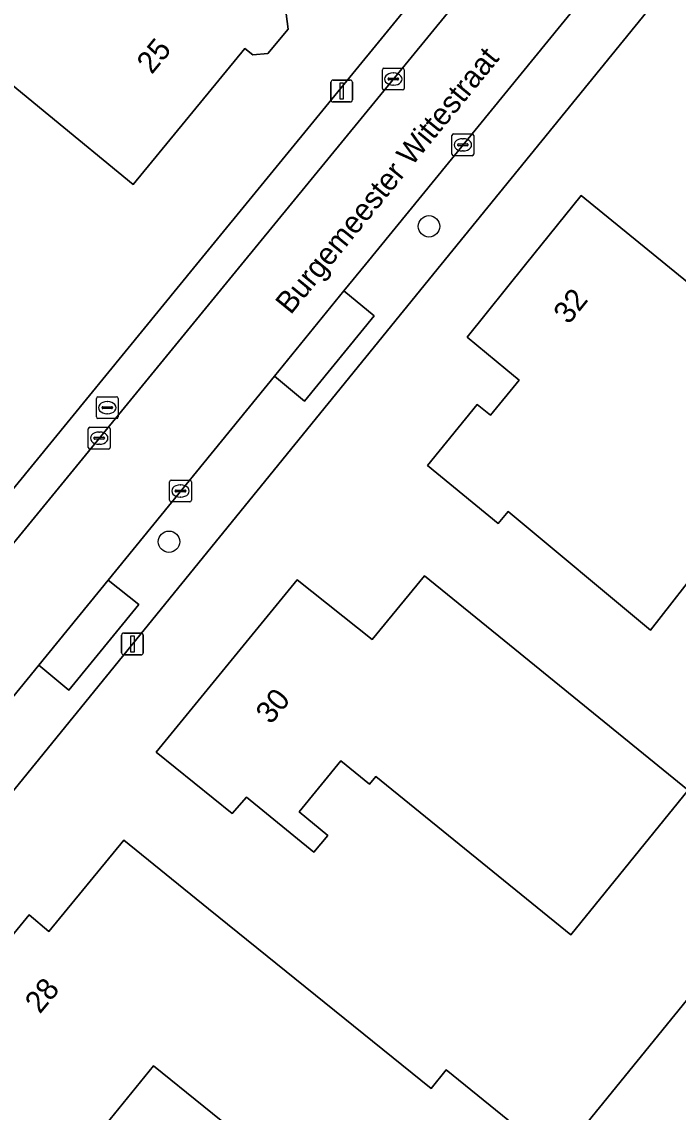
# Model space of a CAD drawing. Extents: x 159499 to 160349, y 382524 to 383273.
# Drawn here: x 160016.05 to 160046.07, y 382961.2 to 383011.11 of the extents above; entities that cross this region are included whole.
import ezdxf

# ---------------------------------------------------------------- set-up
doc = ezdxf.new("R2010")
doc.units = 0
for name, color, linetype in [('IMGEO_Boom', 7, 'Continuous'), ('IMGEO_Brandkraan', 7, 'Continuous'), ('IMGEO_Erf', 7, 'Continuous'), ('IMGEO_Groenvoorziening', 7, 'Continuous'), ('IMGEO_Kolk', 7, 'Continuous'), ('IMGEO_Lichtmast', 7, 'Continuous'), ('IMGEO_Openbare_ruimte_label', 7, 'Continuous'), ('IMGEO_Pand', 7, 'Continuous'), ('IMGEO_Pand_nummerreeks', 7, 'Continuous'), ('IMGEO_Parkeervlak_open', 7, 'Continuous'), ('IMGEO_Rijbaan_lokaal_open', 7, 'Continuous'), ('IMGEO_Voetpad_open', 7, 'Continuous')]:
    doc.layers.add(name, color=color, linetype=linetype)

msp = doc.modelspace()

# ---------------------------------------------------------------- linework, layer by layer
at = {"layer": 'IMGEO_Boom'}
for centre in [(160034.675, 383001.749), (160022.782, 382987.311)]:
    msp.add_circle(centre, 0.489, dxfattribs=at)
at = {"layer": 'IMGEO_Brandkraan'}
for p, q in [((160019.46, 382993.024), (160019.46, 382993.876)), ((160019.535, 382993.95), (160020.387, 382993.95)), ((160020.461, 382993.876), (160020.461, 382993.024)), ((160019.719, 382993.444), (160019.719, 382993.456)), ((160020.157, 382993.407), (160019.759, 382993.407)), ((160019.762, 382993.493), (160020.16, 382993.493)), ((160019.948, 382993.73), (160019.973, 382993.73)), ((160020.203, 382993.456), (160020.203, 382993.444)), ((160020.387, 382992.95), (160019.535, 382992.95)), ((160019.971, 382993.17), (160019.946, 382993.17))]:
    msp.add_line(p, q, dxfattribs=at)
for points in [[(160019.46, 382993.024), (160019.46, 382993.876)], [(160019.535, 382993.95), (160020.387, 382993.95)], [(160020.461, 382993.876), (160020.461, 382993.024)], [(160020.387, 382992.95), (160019.535, 382992.95)]]:
    msp.add_lwpolyline(points, dxfattribs=at)
for centre, radius, start, end in [((160019.537, 382993.874), 0.0765, 91.552, 178.448), ((160019.537, 382993.874), 0.0765, 91.552, 178.448), ((160020.385, 382993.874), 0.0765, 1.552, 88.448), ((160020.385, 382993.874), 0.0765, 1.552, 88.448), ((160019.759, 382993.453), 0.0403, 85.8775, 175.7526), ((160019.756, 382993.443), 0.0366, 178.938, 274.7102), ((160020.16, 382993.45), 0.043, 264.8664, 352.4533), ((160020.164, 382993.455), 0.0386, 1.7309, 96.639), ((160019.537, 382993.026), 0.0765, 181.552, 268.448), ((160019.537, 382993.026), 0.0765, 181.552, 268.448), ((160020.385, 382993.026), 0.0765, 271.552, 358.448), ((160020.385, 382993.026), 0.0765, 271.552, 358.448)]:
    msp.add_arc(centre, radius, start, end, dxfattribs=at)
for centre, major_axis, ratio, start_param, end_param in [((160019.947, 382993.45), (-0.387, 0.002), 0.722429, 4.712389, 7.853982), ((160019.972, 382993.45), (-0.39, 0.002), 0.717154, 1.570796, 4.712389)]:
    msp.add_ellipse(centre, major_axis=major_axis, ratio=ratio, start_param=start_param, end_param=end_param, dxfattribs=at)
at = {"layer": 'IMGEO_Erf'}
for points in [[(160052.413, 382973.653), (160074.019, 383000), (160086.515, 383015.238), (160064.154, 383036.884), (160058.252, 383028.674), (160056.791, 383026.642), (160055.985, 383025.521), (160035.23, 383000), (160013.21, 382972.924), (160006.361, 382964.545)], [(159937.661, 382989.432), (159947.551, 382981.884), (159972.788, 382962.692), (159974.862, 382962.113), (159982.324, 382962.546), (159992.571, 382963.192), (159994.756, 382964.255), (160000, 382970.621), (160005.936, 382977.853), (160024.041, 383000), (160036.566, 383015.316)], [(160028.146, 383011.474), (160028.232, 383010.766), (160027.306, 383009.661), (160026.619, 383009.6), (160026.258, 383009.888), (160021.143, 383003.663), (160017.28, 383006.838), (160013.564, 383009.891), (160017.577, 383014.775)], [(160012.916, 382957.191), (160007.749, 382961.454), (160012.437, 382967.265), (160013.346, 382966.541), (160016.393, 382970.234), (160017.292, 382969.479), (160020.71, 382973.659), (160024.597, 382970.514), (160034.771, 382962.282), (160035.463, 382963.138), (160039.738, 382959.678)], [(160031.009, 382947.305), (160052.413, 382973.653)], [(160031.282, 382955.879), (160022.074, 382963.331), (160017.918, 382958.195)]]:
    msp.add_lwpolyline(points, dxfattribs=at)
for points in [[(160034.602, 382990.807), (160036.885, 382993.599), (160037.483, 382993.104), (160038.802, 382994.704), (160038.198, 382995.204), (160036.42, 382996.676), (160039.09, 383000), (160041.631, 383003.164), (160045.507, 383000), (160054.82, 382992.397), (160051.441, 382988.25), (160049.799, 382989.545), (160048.212, 382987.537), (160048.471, 382987.314), (160047.657, 382986.319), (160047.349, 382986.525), (160044.81, 382983.264), (160038.291, 382988.69), (160037.833, 382988.148)], [(160030.648, 382977.285), (160028.731, 382974.948), (160030.042, 382973.872), (160029.408, 382973.1), (160026.322, 382975.62), (160025.668, 382974.868), (160022.198, 382977.675), (160027.413, 382984.066), (160028.644, 382985.575), (160032.069, 382982.833), (160034.475, 382985.754), (160038.352, 382982.597), (160046.532, 382975.935), (160041.167, 382969.32), (160032.251, 382976.566), (160031.96, 382976.211)]]:
    msp.add_lwpolyline(points, close=True, dxfattribs=at)
at = {"layer": 'IMGEO_Groenvoorziening'}
msp.add_lwpolyline([(160064.767, 383037.736), (160064.154, 383036.884), (160086.515, 383015.238), (160074.019, 383000), (160052.413, 382973.653), (160031.009, 382947.305), (160042.591, 382939.142), (160050.543, 382949.325), (160056.483, 382957.417)], dxfattribs=at)
at = {"layer": 'IMGEO_Kolk'}
for p, q in [((160032.542, 383008.065), (160032.542, 383008.917)), ((160032.617, 383008.991), (160033.469, 383008.991)), ((160033.03, 383008.771), (160033.055, 383008.771)), ((160033.543, 383008.917), (160033.543, 383008.065)), ((160032.801, 383008.485), (160032.801, 383008.497)), ((160033.239, 383008.448), (160032.841, 383008.448)), ((160032.844, 383008.534), (160033.242, 383008.534)), ((160033.285, 383008.497), (160033.285, 383008.485)), ((160033.469, 383007.991), (160032.617, 383007.991)), ((160033.053, 383008.211), (160033.028, 383008.211)), ((160035.724, 383005.053), (160035.724, 383005.905)), ((160035.799, 383005.979), (160036.651, 383005.979)), ((160036.212, 383005.759), (160036.237, 383005.759)), ((160036.725, 383005.905), (160036.725, 383005.053)), ((160035.983, 383005.473), (160035.983, 383005.485)), ((160036.421, 383005.436), (160036.023, 383005.436)), ((160036.026, 383005.522), (160036.424, 383005.522)), ((160036.467, 383005.485), (160036.467, 383005.473)), ((160036.651, 383004.979), (160035.799, 383004.979)), ((160036.235, 383005.199), (160036.21, 383005.199)), ((160019.09, 382991.629), (160019.09, 382992.481)), ((160019.165, 382992.555), (160020.017, 382992.555)), ((160019.578, 382992.335), (160019.603, 382992.335)), ((160020.091, 382992.481), (160020.091, 382991.629)), ((160019.349, 382992.049), (160019.349, 382992.061)), ((160019.787, 382992.012), (160019.389, 382992.012)), ((160019.392, 382992.098), (160019.79, 382992.098)), ((160019.601, 382991.775), (160019.576, 382991.775)), ((160019.833, 382992.061), (160019.833, 382992.049)), ((160020.017, 382991.555), (160019.165, 382991.555)), ((160022.808, 382989.209), (160022.808, 382990.061)), ((160022.883, 382990.135), (160023.735, 382990.135)), ((160023.296, 382989.915), (160023.321, 382989.915)), ((160023.809, 382990.061), (160023.809, 382989.209)), ((160023.067, 382989.629), (160023.067, 382989.641)), ((160023.505, 382989.592), (160023.107, 382989.592)), ((160023.11, 382989.678), (160023.508, 382989.678)), ((160023.319, 382989.355), (160023.294, 382989.355)), ((160023.551, 382989.641), (160023.551, 382989.629)), ((160023.735, 382989.135), (160022.883, 382989.135))]:
    msp.add_line(p, q, dxfattribs=at)
for points in [[(160032.542, 383008.065), (160032.542, 383008.917)], [(160032.617, 383008.991), (160033.469, 383008.991)], [(160033.543, 383008.917), (160033.543, 383008.065)], [(160033.469, 383007.991), (160032.617, 383007.991)], [(160035.724, 383005.053), (160035.724, 383005.905)], [(160035.799, 383005.979), (160036.651, 383005.979)], [(160036.725, 383005.905), (160036.725, 383005.053)], [(160036.651, 383004.979), (160035.799, 383004.979)], [(160019.09, 382991.629), (160019.09, 382992.481)], [(160019.165, 382992.555), (160020.017, 382992.555)], [(160020.091, 382992.481), (160020.091, 382991.629)], [(160020.017, 382991.555), (160019.165, 382991.555)], [(160022.808, 382989.209), (160022.808, 382990.061)], [(160022.883, 382990.135), (160023.735, 382990.135)], [(160023.809, 382990.061), (160023.809, 382989.209)], [(160023.735, 382989.135), (160022.883, 382989.135)]]:
    msp.add_lwpolyline(points, dxfattribs=at)
for centre, radius, start, end in [((160032.619, 383008.915), 0.0765, 91.552, 178.448), ((160032.619, 383008.915), 0.0765, 91.552, 178.448), ((160033.467, 383008.915), 0.0765, 1.552, 88.448), ((160033.467, 383008.915), 0.0765, 1.552, 88.448), ((160032.841, 383008.494), 0.0403, 85.8775, 175.7526), ((160032.838, 383008.484), 0.0366, 178.938, 274.7102), ((160033.242, 383008.491), 0.043, 264.8664, 352.4533), ((160033.246, 383008.496), 0.0386, 1.7309, 96.639), ((160032.619, 383008.067), 0.0765, 181.552, 268.448), ((160032.619, 383008.067), 0.0765, 181.552, 268.448), ((160033.467, 383008.067), 0.0765, 271.552, 358.448), ((160033.467, 383008.067), 0.0765, 271.552, 358.448), ((160035.801, 383005.903), 0.0765, 91.552, 178.448), ((160035.801, 383005.903), 0.0765, 91.552, 178.448), ((160036.649, 383005.903), 0.0765, 1.552, 88.448), ((160036.649, 383005.903), 0.0765, 1.552, 88.448), ((160036.023, 383005.482), 0.0403, 85.8775, 175.7526), ((160036.02, 383005.472), 0.0366, 178.938, 274.7102), ((160036.424, 383005.479), 0.043, 264.8664, 352.4533), ((160036.428, 383005.484), 0.0386, 1.7309, 96.639), ((160035.801, 383005.055), 0.0765, 181.552, 268.448), ((160035.801, 383005.055), 0.0765, 181.552, 268.448), ((160036.649, 383005.055), 0.0765, 271.552, 358.448), ((160036.649, 383005.055), 0.0765, 271.552, 358.448), ((160019.167, 382992.479), 0.0765, 91.552, 178.448), ((160019.167, 382992.479), 0.0765, 91.552, 178.448), ((160020.015, 382992.479), 0.0765, 1.552, 88.448), ((160020.015, 382992.479), 0.0765, 1.552, 88.448), ((160019.389, 382992.058), 0.0403, 85.8775, 175.7526), ((160019.386, 382992.048), 0.0366, 178.938, 274.7102), ((160019.79, 382992.055), 0.043, 264.8664, 352.4533), ((160019.794, 382992.06), 0.0386, 1.7309, 96.639), ((160019.167, 382991.631), 0.0765, 181.552, 268.448), ((160019.167, 382991.631), 0.0765, 181.552, 268.448), ((160020.015, 382991.631), 0.0765, 271.552, 358.448), ((160020.015, 382991.631), 0.0765, 271.552, 358.448), ((160022.885, 382990.059), 0.0765, 91.552, 178.448), ((160022.885, 382990.059), 0.0765, 91.552, 178.448), ((160023.733, 382990.059), 0.0765, 1.552, 88.448), ((160023.733, 382990.059), 0.0765, 1.552, 88.448), ((160023.107, 382989.638), 0.0403, 85.8775, 175.7526), ((160023.104, 382989.628), 0.0366, 178.938, 274.7102), ((160023.508, 382989.635), 0.043, 264.8664, 352.4533), ((160023.512, 382989.64), 0.0386, 1.7309, 96.639), ((160022.885, 382989.211), 0.0765, 181.552, 268.448), ((160022.885, 382989.211), 0.0765, 181.552, 268.448), ((160023.733, 382989.211), 0.0765, 271.552, 358.448), ((160023.733, 382989.211), 0.0765, 271.552, 358.448)]:
    msp.add_arc(centre, radius, start, end, dxfattribs=at)
for centre, major_axis, ratio, start_param, end_param in [((160033.029, 383008.491), (-0.387, 0.002), 0.722429, 4.712389, 7.853982), ((160033.054, 383008.491), (-0.39, 0.002), 0.717154, 1.570796, 4.712389), ((160036.211, 383005.479), (-0.387, 0.002), 0.722429, 4.712389, 7.853982), ((160036.236, 383005.479), (-0.39, 0.002), 0.717154, 1.570796, 4.712389), ((160019.577, 382992.055), (-0.387, 0.002), 0.722429, 4.712389, 7.853982), ((160019.602, 382992.055), (-0.39, 0.002), 0.717154, 1.570796, 4.712389), ((160023.295, 382989.635), (-0.387, 0.002), 0.722429, 4.712389, 7.853982), ((160023.32, 382989.635), (-0.39, 0.002), 0.717154, 1.570796, 4.712389)]:
    msp.add_ellipse(centre, major_axis=major_axis, ratio=ratio, start_param=start_param, end_param=end_param, dxfattribs=at)
at = {"layer": 'IMGEO_Lichtmast'}
for p, q in [((160030.186, 383007.54), (160030.186, 383008.34)), ((160030.186, 383008.34), (160030.186, 383007.54)), ((160030.286, 383008.44), (160031.076, 383008.44)), ((160031.076, 383008.44), (160030.286, 383008.44)), ((160031.176, 383008.34), (160031.176, 383007.54)), ((160031.176, 383007.54), (160031.176, 383008.34)), ((160031.076, 383007.44), (160030.286, 383007.44)), ((160030.286, 383007.44), (160031.076, 383007.44)), ((160020.613, 382982.235), (160020.613, 382983.035)), ((160020.613, 382983.035), (160020.613, 382982.235)), ((160020.713, 382983.135), (160021.503, 382983.135)), ((160021.503, 382983.135), (160020.713, 382983.135)), ((160021.603, 382983.035), (160021.603, 382982.235)), ((160021.603, 382982.235), (160021.603, 382983.035)), ((160021.503, 382982.135), (160020.713, 382982.135)), ((160020.713, 382982.135), (160021.503, 382982.135))]:
    msp.add_line(p, q, dxfattribs=at)
for points in [[(160030.606, 383008.315), (160030.756, 383008.315), (160030.756, 383007.565), (160030.606, 383007.565), (160030.606, 383008.315)], [(160021.033, 382983.01), (160021.183, 382983.01), (160021.183, 382982.26), (160021.033, 382982.26), (160021.033, 382983.01)]]:
    msp.add_lwpolyline(points, dxfattribs=at)
for centre, start, end in [((160030.286, 383008.34), 90, 180), ((160030.286, 383008.34), 90, 180), ((160031.076, 383008.34), 0, 90), ((160031.076, 383008.34), 360, 90), ((160030.286, 383007.54), 180, 270), ((160030.286, 383007.54), 180, 270), ((160031.076, 383007.54), 270, 0), ((160031.076, 383007.54), 270, 0), ((160020.713, 382983.035), 90, 180), ((160020.713, 382983.035), 90, 180), ((160021.503, 382983.035), 0, 90), ((160021.503, 382983.035), 360, 90), ((160020.713, 382982.235), 180, 270), ((160020.713, 382982.235), 180, 270), ((160021.503, 382982.235), 270, 0), ((160021.503, 382982.235), 270, 0)]:
    msp.add_arc(centre, 0.1, start, end, dxfattribs=at)
at = {"layer": 'IMGEO_Pand'}
for points in [[(160026.663, 383014.101), (160026.624, 383014.376), (160028.927, 383017.161), (160028.12, 383017.82), (160025.684, 383019.808), (160023.316, 383021.728), (160021.015, 383018.927), (160018.837, 383018.735), (160017.364, 383016.942), (160017.577, 383014.775), (160013.564, 383009.891), (160017.28, 383006.838), (160021.143, 383003.663), (160026.258, 383009.888), (160026.619, 383009.6), (160027.306, 383009.661), (160028.232, 383010.766), (160028.146, 383011.474), (160026.82, 383012.513)], [(160051.441, 382988.25), (160054.82, 382992.397), (160045.507, 383000), (160041.631, 383003.164), (160039.09, 383000), (160036.42, 382996.676), (160038.198, 382995.204), (160038.802, 382994.704), (160037.483, 382993.104), (160036.885, 382993.599), (160034.602, 382990.807), (160037.833, 382988.148), (160038.291, 382988.69), (160044.81, 382983.264), (160047.349, 382986.525), (160047.657, 382986.319), (160048.471, 382987.314), (160048.212, 382987.537), (160049.799, 382989.545)], [(160027.413, 382984.066), (160022.198, 382977.675), (160025.668, 382974.868), (160026.322, 382975.62), (160029.408, 382973.1), (160030.042, 382973.872), (160028.731, 382974.948), (160030.648, 382977.285), (160031.96, 382976.211), (160032.251, 382976.566), (160041.167, 382969.32), (160046.532, 382975.935), (160038.352, 382982.597), (160034.475, 382985.754), (160032.069, 382982.833), (160028.644, 382985.575)], [(160014.004, 382951.592), (160015.375, 382953.286), (160015.521, 382953.167), (160018.929, 382957.378), (160017.918, 382958.195), (160022.074, 382963.331), (160031.282, 382955.879), (160029.96, 382954.246), (160028.799, 382952.836), (160032.064, 382950.194), (160039.738, 382959.678), (160035.463, 382963.138), (160034.771, 382962.282), (160024.597, 382970.514), (160020.71, 382973.659), (160017.292, 382969.479), (160016.393, 382970.234), (160013.346, 382966.541), (160012.437, 382967.265), (160007.749, 382961.454), (160012.916, 382957.191), (160011.986, 382956.029), (160012.771, 382955.393), (160011.78, 382954.169)]]:
    msp.add_lwpolyline(points, close=True, dxfattribs=at)
at = {"layer": 'IMGEO_Parkeervlak_open'}
for points in [[(160030.786, 382998.795), (160027.604, 382994.891), (160028.981, 382993.743), (160032.171, 382997.658)], [(160016.821, 382981.656), (160018.2, 382980.518), (160021.402, 382984.443), (160020, 382985.559)]]:
    msp.add_lwpolyline(points, close=True, dxfattribs=at)
at = {"layer": 'IMGEO_Rijbaan_lokaal_open'}
for points in [[(160030.786, 382998.795), (160031.767, 383000), (160042.078, 383012.654), (160045.262, 383016.562), (160054.695, 383028.139), (160049.644, 383031.748), (160046.705, 383033.848), (160044.075, 383030.167)], [(160044.82, 383022.879), (160037.807, 383014.31), (160026.095, 383000), (160007.147, 382976.842), (160000, 382968.07), (159996.142, 382963.344)], [(159999.59, 382960.475), (160000, 382960.98), (160004.421, 382966.424), (160007.59, 382970.326), (160016.821, 382981.656), (160020, 382985.559), (160027.604, 382994.891), (160030.786, 382998.795)]]:
    msp.add_lwpolyline(points, dxfattribs=at)
msp.add_lwpolyline([(160035.23, 383000), (160055.985, 383025.521), (160056.791, 383026.642), (160054.695, 383028.139), (160045.262, 383016.562), (160046.669, 383015.431), (160043.484, 383011.526), (160042.078, 383012.654), (160031.767, 383000), (160030.786, 382998.795), (160032.171, 382997.658), (160028.981, 382993.743), (160027.604, 382994.891), (160020, 382985.559), (160021.402, 382984.443), (160018.2, 382980.518), (160016.821, 382981.656), (160007.59, 382970.326), (160008.954, 382969.217), (160005.808, 382965.295), (160006.361, 382964.545), (160013.21, 382972.924)], close=True, dxfattribs=at)
at = {"layer": 'IMGEO_Voetpad_open'}
for points in [[(160026.095, 383000), (160037.807, 383014.31), (160036.846, 383015.097), (160036.566, 383015.316), (160024.041, 383000), (160005.936, 382977.853), (160000, 382970.621), (159994.756, 382964.255), (159992.571, 382963.192), (159982.324, 382962.546), (159982.453, 382960.859), (159989.696, 382961.282), (159992.466, 382961.44)], [(159996.142, 382963.344), (160000, 382968.07), (160007.147, 382976.842), (160026.095, 383000)]]:
    msp.add_lwpolyline(points, dxfattribs=at)

# ---------------------------------------------------------------- texts
at = {"layer": 'IMGEO_Openbare_ruimte_label'}
msp.add_text('Burgemeester Wittestraat', height=1, rotation=50.8033, dxfattribs=at).set_placement((160028.347, 382997.67))
at = {"layer": 'IMGEO_Pand_nummerreeks'}
for s, rotation, p in [('25', 50.5922, (160021.994, 383008.67)), ('32', 51.2294, (160041.064, 382997.219)), ('30', 50.7873, (160027.441, 382978.914)), ('28', 50.4748, (160016.877, 382965.667))]:
    msp.add_text(s, height=1, rotation=rotation, dxfattribs=at).set_placement(p)

doc.saveas('drawing.dxf')
